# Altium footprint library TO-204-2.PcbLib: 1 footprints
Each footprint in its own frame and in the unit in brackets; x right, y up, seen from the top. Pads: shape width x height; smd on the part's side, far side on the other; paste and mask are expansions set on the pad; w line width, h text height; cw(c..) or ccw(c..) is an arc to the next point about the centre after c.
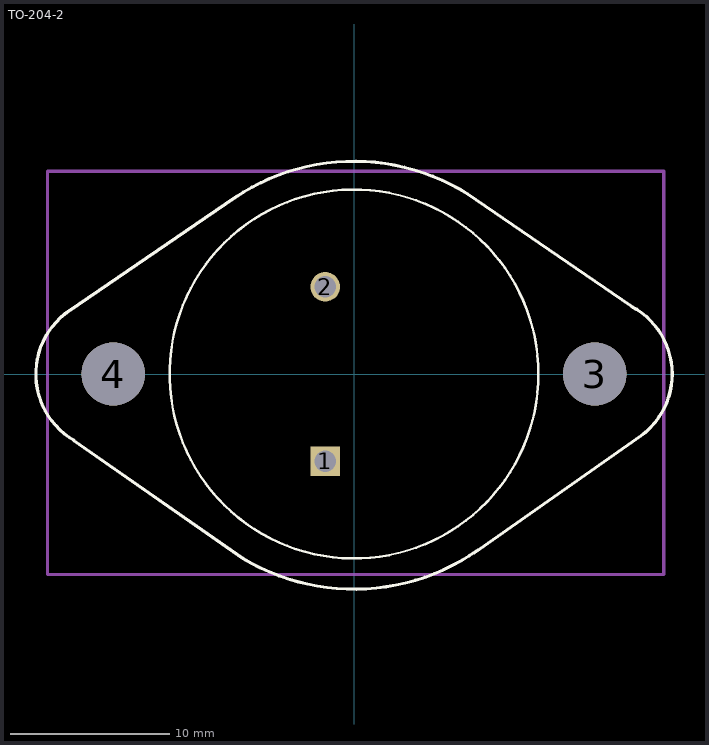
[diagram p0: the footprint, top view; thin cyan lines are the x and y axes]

## TO-204-2 [mil]
pads (4):
  rect 73x73 hole 53: 1(-71,-215)
  round 73 hole 53: 2(-71,215)
  round 156 / inner round 60 / far side round 156 hole 156 unplated paste-78 mask-78: 3(594,0) 4(-594,0)
Top Overlay:
  circle w6: c0,0 r455
  lines w7.87: -703.58,155.24 -293.58,435.24 cw(c0,0) 301.13,430.05 684.74,166.9 cw(c596,0) 785,0 cw(c596,0) 712.36,-148.93 ; -701.69,156.69 ccw(c-596,0) -690.5,-163.68 ; -691.13,-164.58 -273.49,-455.16 ccw(c0,0) 304.57,-434.97 ; 297,-441 720,-144
Mechanical 15:
  lines w7.87: -756,-495 764,-495 764,500 -756,500 -756,-495
3D body "TO-204-2.STEP": height 345, standoff -205, extent -755.43,-500.25 764.07,499.75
